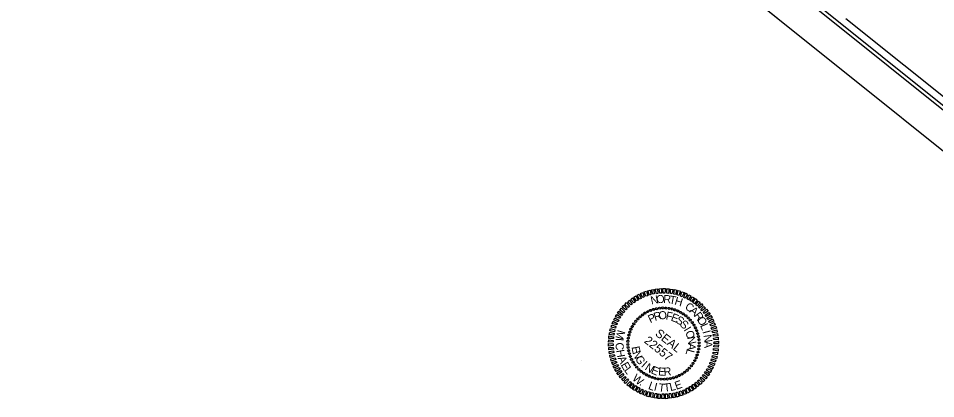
# Model space of a CAD drawing. Extents: x 1732765 to 1738218, y 913652 to 917906.
# Drawn here: x 1733974 to 1735266, y 913652 to 914187 of the extents above; entities that cross this region are included whole.
import ezdxf

# ---------------------------------------------------------------- set-up
doc = ezdxf.new("R2010")
doc.units = 0
for name, color, linetype in [('Prop Roadway Profile Bench Mark Info Text', 7, 'Continuous'), ('Sheet Cutting Line CELL', 7, 'Continuous'), ('Sheet Data Field CELL', 7, 'Continuous'), ('Sheet Plot Border Inside CELL', 7, 'Continuous'), ('Sheet Title CELL', 7, 'Continuous')]:
    doc.layers.add(name, color=color, linetype=linetype)

msp = doc.modelspace()

# ---------------------------------------------------------------- linework, layer by layer
at = {"layer": 'Prop Roadway Profile Bench Mark Info Text'}
for p, q in [((1734864.8, 913776.1), (1734864.8, 913776.1)), ((1734869, 913777.5), (1734869, 913777.5)), ((1734873.2, 913778.6), (1734873.2, 913778.6)), ((1734877.6, 913779.3), (1734877.6, 913779.3)), ((1734881.9, 913779.6), (1734881.9, 913779.6)), ((1734886.3, 913779.4), (1734886.3, 913779.4)), ((1734890.7, 913779), (1734890.7, 913779)), ((1734895, 913778.1), (1734895, 913778.1)), ((1734899.2, 913777), (1734899.2, 913777)), ((1734846.8, 913764), (1734846.8, 913764)), ((1734850, 913767), (1734850, 913767)), ((1734853.4, 913769.8), (1734853.4, 913769.8)), ((1734857, 913772.3), (1734857, 913772.3)), ((1734860.8, 913774.3), (1734860.8, 913774.3)), ((1734903.3, 913775.3), (1734903.3, 913775.3)), ((1734907.2, 913773.4), (1734907.2, 913773.4)), ((1734910.9, 913771.1), (1734910.9, 913771.1)), ((1734914.5, 913768.6), (1734914.5, 913768.6)), ((1734917.8, 913765.6), (1734917.8, 913765.6)), ((1734920.8, 913762.5), (1734920.8, 913762.5)), ((1734839.1, 913753.4), (1734839.1, 913753.4)), ((1734841.3, 913757.2), (1734841.3, 913757.2)), ((1734843.9, 913760.7), (1734843.9, 913760.7)), ((1734923.6, 913759.1), (1734923.6, 913759.1)), ((1734926, 913755.5), (1734926, 913755.5)), ((1734928.1, 913751.6), (1734928.1, 913751.6)), ((1734833.5, 913736.9), (1734833.5, 913736.9)), ((1734834.3, 913741.2), (1734834.3, 913741.2)), ((1734835.5, 913745.4), (1734835.5, 913745.4)), ((1734837.1, 913749.5), (1734837.1, 913749.5)), ((1734929.9, 913747.6), (1734929.9, 913747.6)), ((1734931.3, 913743.5), (1734931.3, 913743.5)), ((1734932.4, 913739.2), (1734932.4, 913739.2)), ((1734832.9, 913728.2), (1734832.9, 913728.2)), ((1734833, 913732.6), (1734833, 913732.6)), ((1734833.2, 913723.8), (1734833.2, 913723.8)), ((1734933, 913734.9), (1734933, 913734.9)), ((1734933.2, 913726.2), (1734933.2, 913726.2)), ((1734933.3, 913730.5), (1734933.3, 913730.5)), ((1734833.8, 913719.5), (1734833.8, 913719.5)), ((1734834.9, 913715.3), (1734834.9, 913715.3)), ((1734836.3, 913711.1), (1734836.3, 913711.1)), ((1734930.7, 913713.3), (1734930.7, 913713.3)), ((1734931.9, 913717.5), (1734931.9, 913717.5)), ((1734932.7, 913721.8), (1734932.7, 913721.8)), ((1734767.6, 913705.7), (1734767.6, 913705.7)), ((1734838.1, 913707.1), (1734838.1, 913707.1)), ((1734840.2, 913703.3), (1734840.2, 913703.3)), ((1734842.6, 913699.6), (1734842.6, 913699.6)), ((1734922.3, 913698), (1734922.3, 913698)), ((1734924.9, 913701.6), (1734924.9, 913701.6)), ((1734927.1, 913705.3), (1734927.1, 913705.3)), ((1734929.1, 913709.2), (1734929.1, 913709.2)), ((1734845.4, 913696.2), (1734845.4, 913696.2)), ((1734848.4, 913693.1), (1734848.4, 913693.1)), ((1734851.7, 913690.2), (1734851.7, 913690.2)), ((1734855.3, 913687.6), (1734855.3, 913687.6)), ((1734859, 913685.4), (1734859, 913685.4)), ((1734909.2, 913686.4), (1734909.2, 913686.4)), ((1734912.8, 913688.9), (1734912.8, 913688.9)), ((1734916.2, 913691.7), (1734916.2, 913691.7)), ((1734919.4, 913694.7), (1734919.4, 913694.7)), ((1734862.9, 913683.4), (1734862.9, 913683.4)), ((1734867, 913681.8), (1734867, 913681.8)), ((1734871.2, 913680.6), (1734871.2, 913680.6)), ((1734875.5, 913679.7), (1734875.5, 913679.7)), ((1734879.9, 913679.3), (1734879.9, 913679.3)), ((1734884.3, 913679.1), (1734884.3, 913679.1)), ((1734888.6, 913679.5), (1734888.6, 913679.5)), ((1734893, 913680.1), (1734893, 913680.1)), ((1734897.2, 913681.2), (1734897.2, 913681.2)), ((1734901.4, 913682.6), (1734901.4, 913682.6)), ((1734905.4, 913684.4), (1734905.4, 913684.4))]:
    msp.add_line(p, q, dxfattribs=at)
for points in [[(1734853.8, 913794.3), (1734850.9, 913799.7), (1734853.9, 913801.3), (1734856, 913795)], [(1734858.4, 913796.1), (1734855.8, 913802), (1734859.1, 913803), (1734860.8, 913796.7)], [(1734863.2, 913797.5), (1734861, 913803.5), (1734864.3, 913804.6), (1734865.4, 913798.3)], [(1734867.9, 913798.7), (1734866.2, 913805), (1734869.5, 913805.7), (1734870.1, 913799.3)], [(1734873, 913799.6), (1734871.5, 913805.9), (1734874.8, 913806.3), (1734875.2, 913799.8)], [(1734877.8, 913800.3), (1734877, 913806.5), (1734880.3, 913806.9), (1734880.1, 913800.2)], [(1734882.8, 913800.3), (1734882.3, 913806.8), (1734885.8, 913806.8), (1734885.1, 913800.2)], [(1734887.7, 913800.4), (1734887.8, 913806.6), (1734891.1, 913806.6), (1734890.1, 913799.9)], [(1734892.7, 913799.7), (1734893, 913806.2), (1734896.5, 913805.6), (1734894.9, 913799.5)], [(1734897.5, 913798.9), (1734898.4, 913805.3), (1734901.7, 913804.5), (1734899.9, 913798.3)], [(1734902.3, 913797.9), (1734903.8, 913804.1), (1734906.8, 913803.2), (1734904.6, 913796.9)], [(1734907.1, 913796.2), (1734909, 913802.4), (1734912, 913801.1), (1734909.2, 913795.4)], [(1734837.2, 913783.7), (1734832.7, 913788.2), (1734835.3, 913790.4), (1734839, 913784.9)], [(1734841.1, 913786.7), (1734836.9, 913791.5), (1734839.5, 913793.7), (1734843, 913787.9)], [(1734845.2, 913789.5), (1734841.4, 913794.7), (1734844.3, 913796.4), (1734847.3, 913790.6)], [(1734849.5, 913791.9), (1734846, 913797.5), (1734849, 913799), (1734851.6, 913793)], [(1734911.8, 913794.3), (1734914, 913800.6), (1734917.1, 913799), (1734913.7, 913793.4)], [(1734916.2, 913792.2), (1734918.9, 913798.2), (1734921.7, 913796.5), (1734918.3, 913791)], [(1734920.4, 913789.8), (1734923.4, 913795.4), (1734926.3, 913793.8), (1734922.5, 913788.5)], [(1734924.6, 913787), (1734928.2, 913792.6), (1734930.7, 913790.5), (1734926.5, 913785.5)], [(1734928.4, 913784), (1734932.3, 913789.2), (1734934.9, 913787.2), (1734930.3, 913782.5)], [(1734826.9, 913772.8), (1734821.5, 913776.5), (1734823.7, 913779.1), (1734828.4, 913774.7)], [(1734830, 913776.7), (1734825, 913780.8), (1734827.2, 913783.3), (1734831.7, 913778.4)], [(1734833.3, 913780.2), (1734828.7, 913784.6), (1734831.1, 913787), (1734835.2, 913781.7)], [(1734932.2, 913780.8), (1734936.5, 913785.7), (1734938.7, 913783.2), (1734933.9, 913779)], [(1734935.5, 913777.2), (1734940.1, 913781.7), (1734942.4, 913779.3), (1734937.2, 913775.5)], [(1734938.8, 913773.3), (1734943.6, 913777.8), (1734945.8, 913775.1), (1734940.2, 913771.5)], [(1734819.3, 913760.2), (1734813.1, 913762.6), (1734814.7, 913765.7), (1734820, 913762.3)], [(1734821.5, 913764.6), (1734815.5, 913767.5), (1734817.3, 913770.4), (1734822.6, 913766.8)], [(1734823.9, 913768.8), (1734818.2, 913772), (1734820.2, 913774.8), (1734825.3, 913770.8)], [(1734941.8, 913769.3), (1734946.8, 913773.3), (1734948.7, 913770.6), (1734943, 913767.5)], [(1734944.3, 913765.2), (1734949.9, 913768.7), (1734951.5, 913766), (1734945.7, 913763.1)], [(1734946.7, 913760.8), (1734952.3, 913764), (1734953.9, 913761), (1734947.8, 913758.7)], [(1734814.1, 913746.1), (1734807.7, 913747.3), (1734808.5, 913750.6), (1734814.7, 913748.5)], [(1734815.5, 913750.9), (1734809.2, 913752.5), (1734810.2, 913755.7), (1734816.1, 913753.2)], [(1734817.2, 913755.7), (1734810.8, 913757.8), (1734812.3, 913760.8), (1734818, 913757.8)], [(1734948.9, 913756.2), (1734954.6, 913759.1), (1734955.9, 913755.9), (1734949.6, 913754.1)], [(1734950.4, 913751.7), (1734956.7, 913754.1), (1734957.5, 913750.9), (1734951.4, 913749.4)], [(1734812.5, 913736.4), (1734805.9, 913736.7), (1734806.3, 913740.1), (1734812.5, 913738.8)], [(1734813.1, 913741.4), (1734806.6, 913742.1), (1734807.4, 913745.4), (1734813.4, 913743.7)], [(1734951.8, 913746.9), (1734958, 913748.9), (1734958.8, 913745.6), (1734952.4, 913744.6)], [(1734952.9, 913742), (1734959.3, 913743.7), (1734959.7, 913740.3), (1734953.5, 913739.7)], [(1734953.6, 913737.1), (1734960, 913738.2), (1734960.3, 913734.8), (1734953.8, 913734.9)], [(1734812, 913731.6), (1734805.6, 913731.2), (1734805.9, 913734.7), (1734812.2, 913733.8)], [(1734812, 913726.7), (1734805.6, 913725.9), (1734805.6, 913729.3), (1734812.1, 913729)], [(1734812.6, 913721.6), (1734806.2, 913720.6), (1734805.9, 913723.9), (1734812.3, 913723.9)], [(1734954.2, 913727.1), (1734960.6, 913727.5), (1734960.3, 913724.1), (1734954, 913724.9)], [(1734954.2, 913732), (1734960.5, 913732.8), (1734960.6, 913729.4), (1734954.1, 913729.7)], [(1734813.3, 913716.7), (1734806.8, 913715.1), (1734806.5, 913718.4), (1734812.7, 913719)], [(1734814.4, 913711.9), (1734808.1, 913709.8), (1734807.3, 913713.1), (1734813.8, 913714.1)], [(1734952, 913712.6), (1734958.5, 913711.4), (1734957.7, 913708.1), (1734951.5, 913710.3)], [(1734953.1, 913717.3), (1734959.6, 913716.6), (1734958.8, 913713.4), (1734952.8, 913715)], [(1734953.7, 913722.3), (1734960.2, 913722.1), (1734959.9, 913718.6), (1734953.7, 913719.9)], [(1734815.8, 913707), (1734809.5, 913704.6), (1734808.7, 913707.8), (1734814.8, 913709.3)], [(1734817.3, 913702.5), (1734811.6, 913699.6), (1734810.3, 913702.9), (1734816.5, 913704.6)], [(1734819.5, 913697.9), (1734813.9, 913694.7), (1734812.3, 913697.7), (1734818.4, 913700.1)], [(1734946.9, 913698.5), (1734953.1, 913696.1), (1734951.5, 913693.1), (1734946.2, 913696.4)], [(1734949, 913703), (1734955.4, 913701), (1734953.9, 913697.9), (1734948.2, 913700.9)], [(1734950.7, 913707.8), (1734957, 913706.2), (1734956, 913703), (1734950.1, 913705.6)], [(1734821.9, 913693.5), (1734816.2, 913690), (1734814.7, 913692.7), (1734820.5, 913695.6)], [(1734824.4, 913689.4), (1734819.4, 913685.4), (1734817.5, 913688.1), (1734823.2, 913691.3)], [(1734827.4, 913685.5), (1734822.6, 913681), (1734820.4, 913683.6), (1734826, 913687.2)], [(1734939.3, 913685.9), (1734944.7, 913682.3), (1734942.5, 913679.6), (1734937.8, 913684.1)], [(1734942.2, 913690), (1734947.9, 913686.7), (1734946, 913683.9), (1734940.9, 913688)], [(1734944.7, 913694.1), (1734950.7, 913691.3), (1734948.9, 913688.4), (1734943.6, 913692)], [(1734830.7, 913681.5), (1734826.1, 913677), (1734823.8, 913679.4), (1734829, 913683.2)], [(1734834, 913678), (1734829.7, 913673.1), (1734827.5, 913675.5), (1734832.3, 913679.7)], [(1734837.8, 913674.7), (1734833.9, 913669.5), (1734831.3, 913671.5), (1734835.9, 913676.2)], [(1734841.5, 913671.7), (1734838, 913666.2), (1734835.5, 913668.2), (1734839.7, 913673.2)], [(1734925.1, 913672.1), (1734929.3, 913667.2), (1734926.7, 913665), (1734923.2, 913670.9)], [(1734929, 913675.1), (1734933.5, 913670.6), (1734930.8, 913668.3), (1734927.2, 913673.8)], [(1734932.8, 913678.5), (1734937.5, 913674.1), (1734935.1, 913671.7), (1734931, 913677)], [(1734936.2, 913682), (1734941.2, 913678), (1734938.9, 913675.4), (1734934.5, 913680.3)], [(1734845.8, 913668.9), (1734842.8, 913663.3), (1734839.9, 913664.9), (1734843.7, 913670.2)], [(1734849.9, 913666.5), (1734847.3, 913660.5), (1734844.5, 913662.3), (1734847.9, 913667.8)], [(1734854.4, 913664.4), (1734852.2, 913658.1), (1734849.1, 913659.7), (1734852.5, 913665.4)], [(1734859.1, 913662.5), (1734857.2, 913656.3), (1734854.2, 913657.6), (1734857, 913663.3)], [(1734863.9, 913660.9), (1734862.4, 913654.6), (1734859.3, 913655.5), (1734861.6, 913661.8)], [(1734868.7, 913659.8), (1734867.8, 913653.4), (1734864.5, 913654.2), (1734866.3, 913660.4)], [(1734873.5, 913659), (1734873.2, 913652.5), (1734869.7, 913653.1), (1734871.3, 913659.3)], [(1734893.2, 913659.1), (1734894.7, 913652.8), (1734891.3, 913652.4), (1734891, 913658.9)], [(1734898.3, 913660), (1734900, 913653.7), (1734896.7, 913653), (1734896, 913659.4)], [(1734903, 913661.2), (1734905.2, 913655.2), (1734901.9, 913654.1), (1734900.8, 913660.5)], [(1734907.8, 913662.6), (1734910.4, 913656.8), (1734907.1, 913655.7), (1734905.4, 913662)], [(1734912.4, 913664.4), (1734915.3, 913659), (1734912.3, 913657.5), (1734910.2, 913663.7)], [(1734916.7, 913666.9), (1734920.2, 913661.3), (1734917.1, 913659.7), (1734914.6, 913665.8)], [(1734921, 913669.2), (1734924.8, 913664), (1734921.9, 913662.3), (1734918.9, 913668.2)], [(1734878.5, 913658.3), (1734878.4, 913652.1), (1734875.1, 913652.1), (1734876.1, 913658.8)], [(1734883.4, 913658.4), (1734883.9, 913651.9), (1734880.4, 913651.9), (1734881.1, 913658.5)], [(1734888.4, 913658.4), (1734889.2, 913652.2), (1734885.9, 913651.8), (1734886.1, 913658.5)]]:
    msp.add_lwpolyline(points, close=True, dxfattribs=at)
for centre, major_axis in [((1734860.8, 913774.3), (-0.64, 1.29)), ((1734864.8, 913776.1), (-0.52, 1.34)), ((1734869, 913777.5), (-0.4, 1.38)), ((1734873.2, 913778.5), (-0.28, 1.41)), ((1734877.6, 913779.2), (-0.16, 1.43)), ((1734881.9, 913779.5), (-0.03, 1.44)), ((1734886.3, 913779.4), (0.09, 1.44)), ((1734890.7, 913778.9), (0.22, 1.42)), ((1734894.9, 913778.1), (0.34, 1.4)), ((1734899.1, 913776.8), (0.46, 1.36)), ((1734903.2, 913775.3), (0.58, 1.32)), ((1734846.8, 913764), (-1.04, 0.99)), ((1734850, 913767), (-0.95, 1.08)), ((1734853.4, 913769.7), (-0.85, 1.16)), ((1734857, 913772.2), (-0.75, 1.23)), ((1734907.2, 913773.3), (0.69, 1.26)), ((1734910.9, 913771.1), (0.8, 1.2)), ((1734914.4, 913768.5), (0.9, 1.12)), ((1734917.7, 913765.6), (0.99, 1.04)), ((1734920.8, 913762.5), (1.08, 0.95)), ((1734837.2, 913749.5), (-1.32, 0.58)), ((1734839.1, 913753.4), (-1.26, 0.69)), ((1734841.3, 913757.1), (-1.2, 0.8)), ((1734843.9, 913760.7), (-1.12, 0.9)), ((1734923.5, 913759), (1.16, 0.85)), ((1734925.9, 913755.4), (1.23, 0.75)), ((1734928, 913751.6), (1.29, 0.64)), ((1734833.5, 913736.9), (-1.42, 0.22)), ((1734834.4, 913741.2), (-1.4, 0.34)), ((1734835.6, 913745.4), (-1.36, 0.46)), ((1734929.8, 913747.6), (1.34, 0.52)), ((1734931.2, 913743.4), (1.38, 0.4)), ((1734932.3, 913739.2), (1.41, 0.28)), ((1734833, 913732.5), (-1.44, 0.09)), ((1734832.9, 913728.2), (-1.44, -0.03)), ((1734833.2, 913723.8), (-1.43, -0.16)), ((1734932.9, 913734.9), (1.43, 0.16)), ((1734933.1, 913726.1), (1.44, -0.09)), ((1734933.2, 913730.5), (1.44, 0.03)), ((1734833.9, 913719.5), (-1.41, -0.28)), ((1734835, 913715.2), (-1.38, -0.4)), ((1734836.4, 913711.1), (-1.34, -0.52)), ((1734929, 913709.2), (1.32, -0.58)), ((1734930.6, 913713.3), (1.36, -0.46)), ((1734931.8, 913717.5), (1.4, -0.34)), ((1734932.7, 913721.8), (1.42, -0.22)), ((1734838.1, 913707.1), (-1.29, -0.64)), ((1734840.2, 913703.2), (-1.23, -0.75)), ((1734842.7, 913699.6), (-1.16, -0.85)), ((1734922.3, 913698), (1.12, -0.9)), ((1734924.8, 913701.5), (1.2, -0.8)), ((1734927.1, 913705.3), (1.26, -0.69)), ((1734845.4, 913696.2), (-1.08, -0.95)), ((1734848.5, 913693), (-0.99, -1.04)), ((1734851.7, 913690.2), (-0.9, -1.12)), ((1734855.3, 913687.6), (-0.8, -1.2)), ((1734859, 913685.3), (-0.69, -1.26)), ((1734863, 913683.4), (-0.58, -1.32)), ((1734905.3, 913684.4), (0.64, -1.29)), ((1734909.2, 913686.5), (0.75, -1.23)), ((1734912.8, 913688.9), (0.85, -1.16)), ((1734916.2, 913691.7), (0.95, -1.08)), ((1734919.4, 913694.7), (1.04, -0.99)), ((1734867, 913681.8), (-0.46, -1.36)), ((1734871.2, 913680.6), (-0.34, -1.4)), ((1734875.5, 913679.7), (-0.22, -1.42)), ((1734879.9, 913679.3), (-0.09, -1.44)), ((1734884.3, 913679.2), (0.03, -1.44)), ((1734888.6, 913679.5), (0.16, -1.43)), ((1734892.9, 913680.1), (0.28, -1.41)), ((1734897.2, 913681.2), (0.4, -1.38)), ((1734901.3, 913682.6), (0.52, -1.34))]:
    msp.add_ellipse(centre, major_axis=major_axis, ratio=0.999708, dxfattribs=at)
at = {"layer": 'Sheet Cutting Line CELL'}
msp.add_line((1732765.3, 916010.8), (1735394.8, 913906.4), dxfattribs=at)
at = {"layer": 'Sheet Data Field CELL'}
msp.add_lwpolyline([(1736769.5, 915624), (1734139.9, 917728.5), (1732765.3, 916010.8), (1735394.8, 913906.4)], close=True, dxfattribs=at)
at = {"layer": 'Sheet Plot Border Inside CELL'}
msp.add_lwpolyline([(1732813.6, 916029.6), (1735415.9, 913947), (1736734.4, 915594.6), (1734132.1, 917677.2)], close=True, dxfattribs=at)
at = {"layer": 'Sheet Title CELL'}
for points in [[(1733072.9, 915828.7), (1735383.9, 913979.1)], [(1735140, 914187.2), (1735382.4, 913993.2)]]:
    msp.add_lwpolyline(points, dxfattribs=at)

# ---------------------------------------------------------------- texts
at = {"layer": 'Prop Roadway Profile Bench Mark Info Text'}
for s, height, rotation, p in [('N', 11.3, 11.7532, (1734866.1, 913784.2)), ('O', 11.3, 4.5514, (1734873.3, 913786)), ('R', 11.3, 357.3502, (1734882.6, 913786.6)), ('T', 11.3, 350.1494, (1734890.6, 913786)), ('H', 11.3, 342.9492, (1734897.8, 913784.6)), ('C', 11.3, 328.5495, (1734912.3, 913778.5)), ('A', 11.3, 321.35, (1734918.9, 913774.1)), ('P', 11.3, 25.7286, (1734864.5, 913758)), ('R', 11.3, 16.3693, (1734871, 913761.2)), ('O', 11.3, 7.0109, (1734876.8, 913763)), ('F', 11.3, 348.2967, (1734885.6, 913763.6)), ('E', 11.3, 338.9407, (1734892.6, 913762)), ('S', 11.3, 329.5853, (1734899.3, 913759.5)), ('R', 11.3, 306.9508, (1734925.3, 913768.7)), ('O', 11.3, 299.7508, (1734929.7, 913763.4)), ('S', 11.3, 320.2301, (1734905, 913755.1)), ('I', 11.3, 301.5193, (1734911, 913748.8)), ('L', 11.3, 292.5506, (1734934.4, 913755)), ('M', 11.3, 253.4813, (1734818.7, 913749.4)), ('22557', 12, 321.3297, (1734854.9, 913731.6)), ('SEAL', 12, 321.3297, (1734870.3, 913741.7)), ('O', 11.3, 292.1632, (1734913.3, 913745.2)), ('N', 11.3, 282.8063, (1734916.1, 913738)), ('I', 11.3, 285.3498, (1734937.9, 913746.3)), ('N', 11.3, 278.1486, (1734939.3, 913741.2)), ('C', 11.3, 273.3651, (1734815.4, 913730.6)), ('I', 11.3, 266.7372, (1734816, 913737.4)), ('E', 11.3, 280.6066, (1734838, 913724.6)), ('A', 11.3, 264.0899, (1734917.5, 913730.4)), ('A', 11.3, 270.9468, (1734940.4, 913732.9)), ('H', 11.3, 279.993, (1734816.3, 913719.8)), ('N', 11.3, 289.9636, (1734839.4, 913716.7)), ('G', 11.3, 299.3199, (1734842.7, 913708.5)), ('L', 11.3, 254.7305, (1734916.3, 913722.5)), ('A', 11.3, 293.2489, (1734818.4, 913709)), ('E', 11.3, 299.8768, (1734822.5, 913699.4)), ('I', 11.3, 318.0309, (1734850.8, 913697.5)), ('N', 11.3, 327.3861, (1734855.9, 913693.1)), ('E', 11.3, 336.7414, (1734864.5, 913688)), ('L', 11.3, 306.5047, (1734827, 913691.8)), ('W', 11.3, 319.7606, (1734838.1, 913679)), ('E', 11.3, 355.4538, (1734875.2, 913684.7)), ('R', 11.3, 4.8111, (1734883.7, 913684)), ('.', 11.3, 333.0164, (1734848.3, 913671.4)), ('L', 11.3, 339.6443, (1734860.7, 913665.7)), ('I', 11.3, 346.2723, (1734868.8, 913663.5)), ('T', 11.3, 352.9002, (1734875.4, 913662.3)), ('T', 11.3, 6.156, (1734884.1, 913661.6)), ('L', 11.3, 12.7839, (1734892.9, 913662.4)), ('E', 11.3, 19.4119, (1734901.1, 913664.2))]:
    msp.add_text(s, height=height, rotation=rotation, dxfattribs=at).set_placement(p)

doc.saveas('drawing.dxf')
